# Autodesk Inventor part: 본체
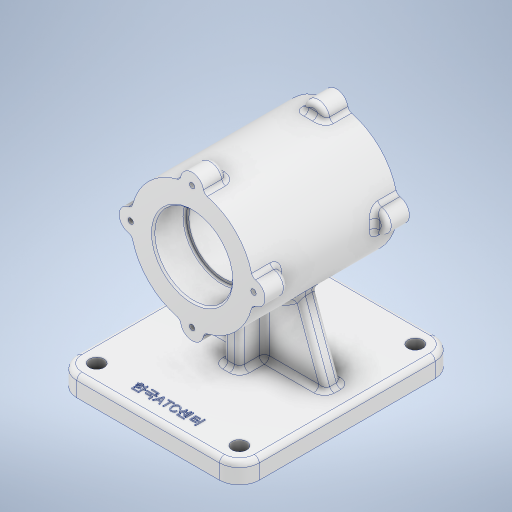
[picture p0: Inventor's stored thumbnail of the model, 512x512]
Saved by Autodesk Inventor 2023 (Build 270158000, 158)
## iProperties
Created: 2023-08
Part Number: 본체
Material: 알루미늄 6061
Document SubType Name: Modeling
Designer: asung
Density: 2.7 g/cm^3
Appearance: 알루미늄 - 평지
Mass: 1218.04 g
Surface Area: 798.427 cm^2
Volume: 451.126 cm^3
Author: asung
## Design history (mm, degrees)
sketch "스케치1"
  geometry: L1 (43, -65)-(-43, -65); L2 (-55, -53)-(-55, 53); L3 (-43, 65)-(43, 65); L4 (55, 53)-(55, -53); L5 (55, -65)-(-55, 65); L6 (-55, -65)-(55, 65); C1 r 4.5 at (43, 53); C2 r 4.5 at (43, -53); C3 r 4.5 at (-43, -53); C4 r 4.5 at (-43, 53); A1 r 12 centre (43, 53) between (55, 53) and (43, 65); A2 r 12 centre (43, -53) between (43, -65) and (55, -53); A3 r 12 centre (-43, -53) between (-55, -53) and (-43, -65); A4 r 12 centre (-43, 53) between (-43, 65) and (-55, 53); 1 further point
  constraints: 12 end point, 8 centre point, 8 point on circle, 8 point on line, 8 tangent, 4 coincident, 3 equal radius, 2 midpoint, 2 parallel, 1 horizontal, 1 perpendicular
  dimensions: "d0" = 110 distance of L5.end L6.end; "d1" = 130 distance of L6.start L5.end; "d2" = 12 radius of A1; "d3" = 9 diameter of C1; "d4" = 9 diameter of C2; "d5" = 9 diameter of C3; "d6" = 9 diameter of C4
extrude "돌출1" new body sketch "스케치1" distance "d7" = 12; taper "d8" = 0 deg
node "작업 평면1"
sketch "스케치2"
  geometry: L1 (43, 0)-(43, 82); C1 r 37 at (43, 82)
  constraints: 2 end point, 1 centre point, 1 coincident, 1 vertical
  dimensions: "d10" = 82 distance of L1.start L1.end; "d11" = 74 diameter of C1
extrude "돌출2" join sketch "스케치2" stored distance "d12" = 87; taper "d13" = 0 deg
sketch "스케치3"
  geometry: C1 r 37 at (0, 0) reference; 2 further points
  constraints: 1 coincident
hole "구멍1" sketch "스케치3" at (0, 0) diameter "d14" = 42; stored, may be unused: countersink angle "d18" = 82 deg, drill point angle "d20" = 0 deg; dims "d15" = 8, "d16" = 47, "d17" = 19, "d19" = 87
sketch "스케치4"
  geometry: C1 r 37 at (0, 0) reference; 2 further points
  constraints: 1 coincident
hole "구멍2" sketch "스케치4" at (0, 0) diameter "d21" = 42; stored, may be unused: countersink angle "d25" = 90 deg, drill point angle "d27" = 0 deg; dims "d22" = 6, "d23" = 47, "d24" = 19, "d26" = 87
chamfer "모따기1" distance "d28" = 1; stored, may be unused: second distance "d29" = 2, angle "d30" = 45 deg
sketch "스케치5"
  geometry: 1 further point
sketch "스케치6"
  geometry: C1 r 37 at (0, 0) reference; C2 r 7 at (0, 37); 2 further points
  constraints: 1 centre point, 1 vertical alignment, 1 other
  dimensions: "d31" = 14 diameter of C2
extrude "돌출3" join sketch "스케치6" distance "d32" = 14; taper "d33" = 0 deg
fillet "모깎기1" dims "d34" = 3
fillet "모깎기2" dims "d35" = 3
sketch "스케치7"
  geometry: A1 r 7 centre (43, 119) between (49.889, 120.239) and (36.111, 120.239) reference; 2 further points
  constraints: 1 coincident
hole "구멍3" sketch "스케치7" at (43, 119) diameter "d36" = 3.242; stored, may be unused: countersink angle "d40" = 90 deg, drill point angle "d42" = 118 deg; dims "d37" = 8, "d38" = 47, "d39" = 19, "d41" = 10
node "작업 평면2"
sketch "스케치8"
  geometry: L1 (-43, -65)-(43, -65) reference; L2 (0, -65)-(0, 5); L3 (5, -15)-(-5, -15); L4 (-5, -15)-(-5, 25); L5 (-5, 25)-(5, 25); L6 (5, 25)-(5, -15); L7 (5, -15)-(-5, 25); L8 (-5, -15)-(5, 25); 1 further point
  constraints: 14 end point, 3 midpoint, 2 parallel, 1 horizontal, 1 perpendicular, 1 vertical
  dimensions: "d46" = 70 distance of L2.start L2.end; "d47" = 10 distance of L4.end L5.end; "d48" = 40 distance of L3.end L4.end
extrude "돌출4" join sketch "스케치8" stored distance "d49" = 14; taper "d50" = 0 deg
node "작업 평면3"
sketch "스케치10"
  geometry: L1 (-12, 0)-(-12, 12) reference; L2 (16.837, 55.837)-(0.882, 12); L3 (0, 12)-(-12, 12) reference; L4 (69.163, 55.837)-(85.118, 12); A1 r 37 centre (43, 82) between (7.138, 72.896) and (33.896, 46.138) reference; 1 further point
  constraints: 4 end point, 1 point on circle, 1 point on line
  dimensions: "d64" = 110 deg angle of L3 L2
feature "리브2" dims "d65" = 1, "d66" = 10, "d67" = 0, "d68" = 0, "d69" = 1, "d70" = 1
feature "리브3" dims "d71" = 1, "d72" = 10, "d73" = 0, "d74" = 0, "d75" = 1, "d76" = 1
sketch "스케치11"
  geometry: 1 further point
fillet "모깎기3" dims "d77" = 3
fillet "모깎기4" dims "d78" = 3
fillet "모깎기5" dims "d79" = 3
fillet "모깎기6" dims "d80" = 3
sketch "스케치12"
  geometry: L1 (-52, 53)-(-52, -53) reference; L2 (-43, -62)-(43, -62) reference; L3 (52, -53)-(52, 53) reference; L4 (43, 62)-(-43, 62) reference; L5 (37.834, 13)-(8, 13) reference; L6 (8, 13)-(8, 22) reference; L7 (2, 28)-(-2, 28) reference; L8 (-8, 22)-(-8, 13) reference; L9 (-8, 13)-(-37.834, 13) reference; L10 (-44.219, 7)-(-44.219, 3) reference; L11 (-37.834, -3)-(-8, -3) reference; L12 (-8, -3)-(-8, -12) reference; L13 (-2, -18)-(2, -18) reference; L14 (8, -12)-(8, -3) reference; L15 (8, -3)-(37.834, -3) reference; L16 (44.219, 3)-(44.219, 7) reference; L17 (77, 5)-(-77, 5) reference; L18 (-55, 53)-(-55, -53) reference; C1 r 4.5 at (-43, -53) reference; C2 r 4.5 at (-43, 53) reference; C3 r 4.5 at (43, 53) reference; C4 r 4.5 at (43, -53) reference; A1 r 9 centre (-43, 53) between (-43, 62) and (-52, 53) reference; A2 r 9 centre (-43, -53) between (-52, -53) and (-43, -62) reference; A3 r 9 centre (43, -53) between (43, -62) and (52, -53) reference; A4 r 9 centre (43, 53) between (52, 53) and (43, 62) reference; A5 r 6 centre (2, 22) between (8, 22) and (2, 28) reference; A6 r 6 centre (-2, 22) between (-2, 28) and (-8, 22) reference; A7 r 6 centre (-2, -12) between (-8, -12) and (-2, -18) reference; A8 r 6 centre (2, -12) between (2, -18) and (8, -12) reference; 2 further points
  constraints: 5 other
  dimensions: "d81" = 58 distance from line of point (0, -53) L17; "d83" = 55 distance from line of L18 point (0, -53)
  node "절단 모서리 투영1"
sketch "스케치13"
  geometry: 1 further point
sketch "스케치14"
  geometry: 1 further point
node "작업 평면4"
sketch "스케치15"
  geometry: 1 further point
sketch "스케치16"
  geometry: 1 further point
feature "엠보싱1" dims "d84" = 0.5, "d85" = 0
fillet "모깎기7" dims "d86" = 1
feature "˺耀˼耀˾耀̀耀̂耀̄耀̆耀̈耀" dims "d0" = 110, "d1" = 130, "d2" = 12, "d3" = 9, "d4" = 9, "d5" = 9, "d6" = 9, "d7" = 12, "d8" = 0, "d9" = -70, "d10" = 82, "d11" = 74, "d12" = 87, "d13" = 0, "d14" = 42, "d15" = 8, "d16" = 47, "d17" = 19, "d18" = 82 deg, "d19" = 87, "d20" = 0, "d21" = 42, "d22" = 6, "d23" = 47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
node "솔리드1"
pattern_circular "원형 패턴1" dims "d44" = 360 deg
mirror "미러1"
feature "A9D066F2-1C7D-4E18-AEED-F7BC21143FA4" dims "d14" = 42, "d15" = 8, "d16" = 47, "d17" = 19, "d18" = 82 deg, "d19" = 87, "d20" = 0
